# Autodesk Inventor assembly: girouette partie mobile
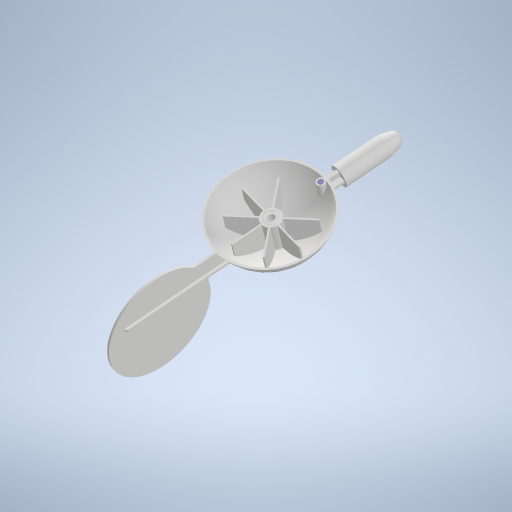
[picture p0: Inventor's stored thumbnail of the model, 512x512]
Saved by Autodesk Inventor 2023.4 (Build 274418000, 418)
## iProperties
Created: 2024-03
Part Number: girouette partie mobile
Document SubType Name: Assembly
Designer: mel
Author: mel
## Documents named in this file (4)
- D:\travail\année 2023-2024\IT\char à voile\girouette partie mobile.iam
- D:\travail\année 2023-2024\IT\char à voile\aimant.ipt
- D:\travail\année 2023-2024\IT\char à voile\contrevent.ipt
- D:\travail\année 2023-2024\IT\char à voile\145988124-9-skf_bearing_w_638_4_x-2z_2\skf_bearing_w_638_4_x-2z_2.iam
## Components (3 placed, 3 different names)
1. aimant:1 — Logement:1
2. contrevent:1 — Logement:1, Logement:2
3. skf_bearing_w_638_4_x-2z_2:1 [sub-assembly] — Logement:2
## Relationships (2: Insert 2)
- Logement:1 [Insert]: aimant:1 ↔ contrevent:1
- Logement:2 [Insert]: contrevent:1 ↔ skf_bearing_w_638_4_x-2z_2:1
